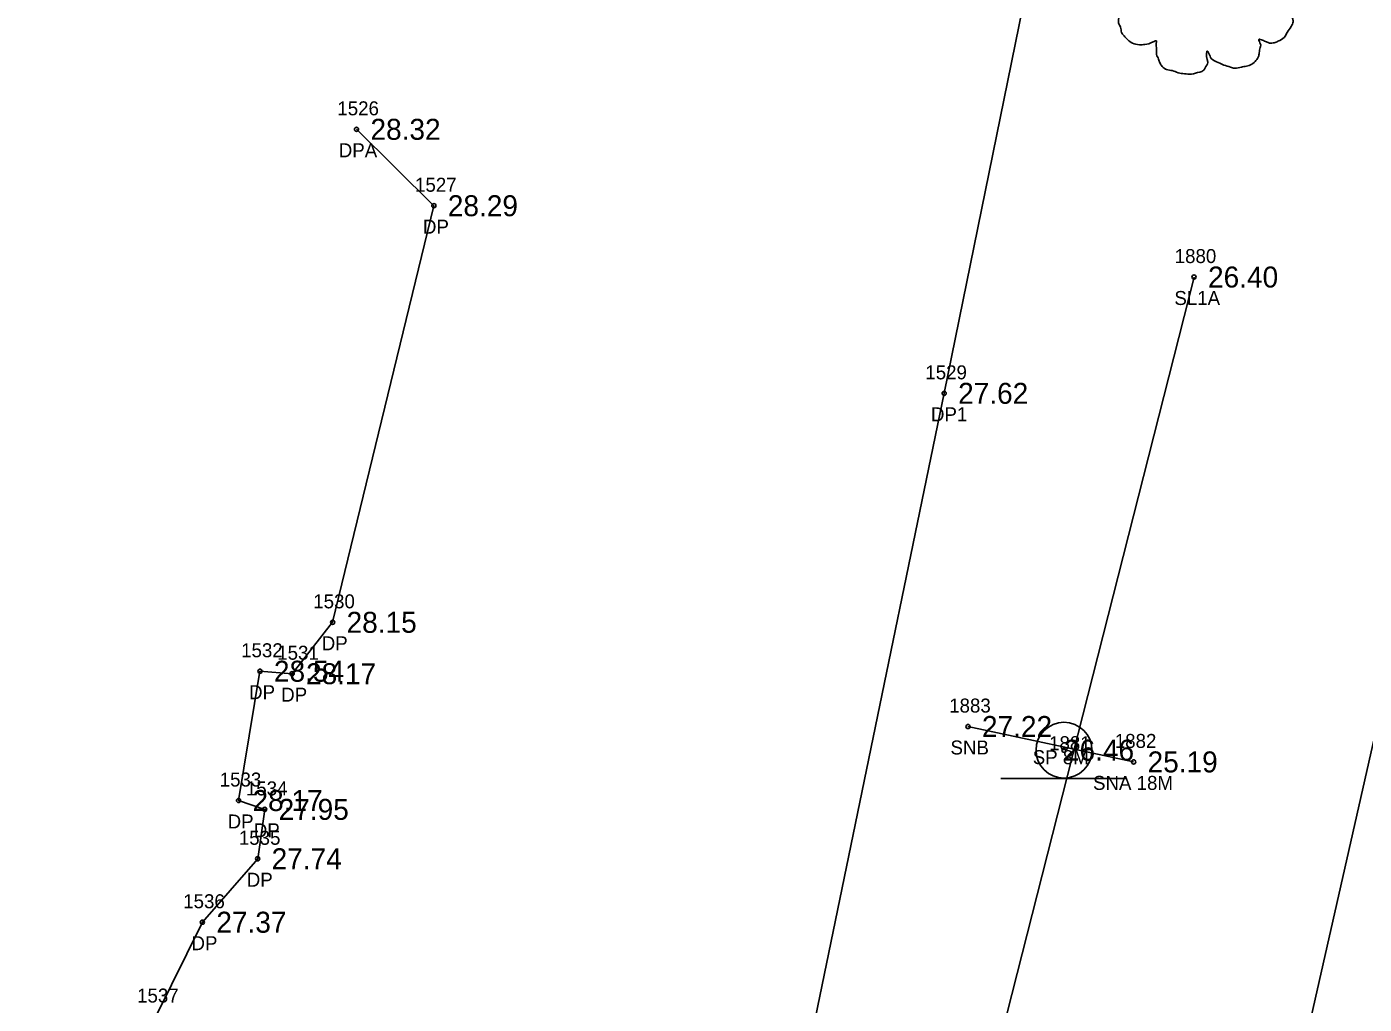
# Model space of a CAD drawing. Extents: x 2654414 to 2656963, y 761776 to 764965.
# Drawn here: x 2655478.7 to 2655574.4, y 762657.4 to 762727.3 of the extents above; entities that cross this region are included whole.
import ezdxf

# ---------------------------------------------------------------- set-up
doc = ezdxf.new("R2010")
doc.units = 0
for name, color, linetype in [('RD_EX_BldgApp', 7, 'Continuous'), ('RD_EX_BldgApp_txCode', 7, 'Continuous'), ('RD_EX_Driveway', 7, 'Continuous'), ('RD_EX_Driveway_txCode', 7, 'Continuous'), ('RD_EX_Road', 7, 'Continuous'), ('RD_EX_TX_BldgApp_ELEV', 7, 'Continuous'), ('RD_EX_TX_Driveway_ELEV', 7, 'Continuous'), ('RD_EX_TX_VEG_ELEV', 7, 'Continuous'), ('RD_EX_VEG', 7, 'Continuous'), ('RD_EX_VEG_txCode', 7, 'Continuous'), ('RD_SMD_Locator', 7, 'Continuous')]:
    doc.layers.add(name, color=color, linetype=linetype)

msp = doc.modelspace()

# ---------------------------------------------------------------- linework, layer by layer
at = {"layer": 'RD_EX_BldgApp'}
for p, q in [((2655557.902, 762674.701), (2655546.048, 762677.232)), ((2655548.4, 762673.514), (2655557.4, 762673.514))]:
    msp.add_line(p, q, dxfattribs=at)
msp.add_circle((2655552.917, 762675.539), 2, dxfattribs=at)
at = {"layer": 'RD_EX_Driveway'}
for points in [[(2655598.992, 762783.09), (2655591.737, 762789.455), (2655575.978, 762787.383), (2655565.187, 762780.326), (2655555.27, 762759.9), (2655550.243, 762730.015), (2655544.342, 762701.065), (2655531.318, 762637.943), (2655527.698, 762630.476), (2655527.209, 762614.176), (2655533.681, 762601.366), (2655541.257, 762592.29), (2655549.192, 762591.56), (2655556.356, 762593.843)], [(2655502.283, 762719.95), (2655507.82, 762714.483), (2655500.575, 762684.686), (2655497.674, 762681.01), (2655495.375, 762681.187), (2655493.84, 762671.94), (2655495.714, 762671.306), (2655495.211, 762667.773), (2655491.253, 762663.235), (2655487.927, 762656.49), (2655481.104, 762632.763), (2655485.711, 762616.615), (2655484.296, 762604.909), (2655505.68, 762598.432), (2655526.949, 762586.383), (2655538.158, 762577.446), (2655543.819, 762568.024), (2655548.114, 762557.141)]]:
    msp.add_lwpolyline(points, dxfattribs=at)
at = {"layer": 'RD_EX_Road'}
msp.add_lwpolyline([(2655700.994, 763232.279), (2655693.552, 763198.573), (2655671.649, 763102.037), (2655649.038, 763001.061), (2655627.271, 762906.233), (2655604.996, 762809.365), (2655598.992, 762783.09), (2655583.655, 762714.137), (2655561.97, 762618.323), (2655556.356, 762593.843), (2655548.114, 762557.141), (2655540.102, 762522.478), (2655518.03, 762425.04), (2655496.479, 762329.558), (2655475.552, 762236.625), (2655473.199, 762226.142), (2655466.574, 762197.504), (2655460.058, 762168.164), (2655454.261, 762143.776), (2655432.5, 762049.878), (2655410.7, 761955.515), (2655388.166, 761858.426), (2655373.501, 761793.951)], dxfattribs=at)
at = {"layer": 'RD_EX_VEG'}
msp.add_lwpolyline([(2655562.228, 762709.383), (2655542.674, 762632.468), (2655541.868, 762617.651)], dxfattribs=at)
for points in [[(2655562.787, 762738.466), (2655562.487, 762738.491), (2655562.162, 762738.391), (2655561.913, 762738.291), (2655561.688, 762738.216), (2655561.463, 762738.116), (2655561.163, 762737.941), (2655560.938, 762737.741), (2655560.813, 762737.491), (2655560.763, 762737.266), (2655560.713, 762736.992), (2655560.713, 762736.817), (2655560.588, 762736.792), (2655560.438, 762736.817), (2655560.188, 762736.892), (2655559.938, 762736.892), (2655559.688, 762736.892), (2655559.339, 762736.867), (2655558.989, 762736.867), (2655558.714, 762736.817), (2655558.389, 762736.767), (2655558.014, 762736.642), (2655557.664, 762736.517), (2655557.365, 762736.267), (2655557.115, 762735.792), (2655556.99, 762735.442), (2655556.84, 762735.192), (2655556.99, 762734.743), (2655557.165, 762734.393), (2655557.19, 762734.193), (2655557.265, 762733.768), (2655557.365, 762733.543), (2655557.489, 762733.343), (2655557.415, 762733.318), (2655557.04, 762733.268), (2655556.74, 762733.168), (2655556.315, 762732.943), (2655556.09, 762732.718), (2655555.99, 762732.394), (2655555.965, 762732.044), (2655555.865, 762731.844), (2655555.79, 762731.569), (2655555.765, 762731.494), (2655555.715, 762731.169), (2655555.815, 762730.719), (2655555.84, 762730.369), (2655555.965, 762730.145), (2655556.115, 762729.97), (2655556.29, 762729.72), (2655556.69, 762729.495), (2655557.015, 762729.395), (2655557.215, 762729.37), (2655557.04, 762728.87), (2655556.99, 762728.52), (2655556.865, 762728.12), (2655556.865, 762728.046), (2655556.815, 762727.571), (2655556.965, 762727.246), (2655557.04, 762726.871), (2655557.215, 762726.646), (2655557.489, 762726.346), (2655557.814, 762726.121), (2655558.314, 762725.996), (2655558.714, 762726.021), (2655559.289, 762726.196), (2655559.539, 762726.271), (2655559.514, 762726.096), (2655559.539, 762725.721), (2655559.539, 762725.297), (2655559.688, 762724.972), (2655559.788, 762724.697), (2655559.938, 762724.447), (2655560.263, 762724.222), (2655560.663, 762724.147), (2655561.088, 762723.997), (2655561.538, 762723.922), (2655562.037, 762723.897), (2655562.637, 762724.047), (2655562.912, 762724.172), (2655563.012, 762724.347), (2655563.212, 762724.722), (2655563.162, 762724.947), (2655563.187, 762725.547), (2655563.287, 762725.372), (2655563.462, 762725.022), (2655563.962, 762724.722), (2655564.361, 762724.547), (2655564.836, 762724.397), (2655565.136, 762724.322), (2655565.611, 762724.397), (2655565.986, 762724.472), (2655566.361, 762724.597), (2655566.66, 762724.872), (2655566.835, 762725.147), (2655566.885, 762725.422), (2655566.96, 762725.796), (2655567.01, 762725.971)], [(2655567.01, 762725.971), (2655566.935, 762726.146), (2655566.885, 762726.396), (2655566.96, 762726.371), (2655567.135, 762726.321), (2655567.41, 762726.196), (2655567.635, 762726.121), (2655567.96, 762726.146), (2655568.235, 762726.246), (2655568.685, 762726.521), (2655568.959, 762726.996), (2655569.234, 762727.396), (2655569.309, 762727.721), (2655569.259, 762727.946), (2655569.234, 762728.445), (2655569.034, 762728.695), (2655568.984, 762728.82), (2655568.884, 762729.22), (2655568.959, 762729.27), (2655569.234, 762729.32), (2655569.609, 762729.445), (2655569.884, 762729.57), (2655570.109, 762729.745), (2655570.184, 762729.97), (2655570.159, 762730.369), (2655570.209, 762730.769), (2655570.134, 762730.919), (2655570.034, 762731.069), (2655569.959, 762731.269), (2655569.809, 762731.419), (2655569.709, 762731.569), (2655569.609, 762731.669), (2655569.484, 762731.819), (2655569.309, 762731.944), (2655569.159, 762731.994), (2655569.109, 762732.144), (2655569.259, 762732.344), (2655569.309, 762732.444), (2655569.334, 762732.668), (2655569.559, 762733.018), (2655569.609, 762733.418), (2655569.559, 762733.843), (2655569.509, 762734.118), (2655569.359, 762734.393), (2655569.159, 762734.643), (2655569.034, 762734.818), (2655568.859, 762734.942), (2655568.535, 762735.067), (2655568.285, 762735.117), (2655567.935, 762735.117), (2655567.735, 762735.167), (2655567.76, 762735.217), (2655567.76, 762735.367), (2655567.76, 762735.642), (2655567.685, 762736.092), (2655567.535, 762736.592), (2655567.535, 762736.617), (2655567.435, 762736.867), (2655567.21, 762737.067), (2655567.035, 762737.166), (2655566.835, 762737.291), (2655566.585, 762737.316), (2655566.286, 762737.316), (2655566.011, 762737.266), (2655565.811, 762737.166), (2655565.636, 762737.042), (2655565.561, 762737.191), (2655565.461, 762737.491), (2655565.411, 762737.641), (2655565.261, 762737.816), (2655565.036, 762738.016), (2655564.586, 762738.141), (2655563.962, 762738.066), (2655563.662, 762737.866), (2655563.512, 762737.691), (2655563.462, 762737.816), (2655563.262, 762738.016), (2655563.162, 762738.191), (2655562.987, 762738.316), (2655562.837, 762738.416), (2655562.737, 762738.466)]]:
    msp.add_spline(points, degree=3, dxfattribs=at)
at = {"layer": 'RD_SMD_Locator'}
for centre in [(2655502.283, 762719.95), (2655507.82, 762714.483), (2655562.228, 762709.383), (2655544.342, 762701.065), (2655500.575, 762684.686), (2655495.375, 762681.187), (2655497.674, 762681.01), (2655546.048, 762677.232), (2655552.917, 762675.539), (2655557.902, 762674.701), (2655493.84, 762671.94), (2655495.714, 762671.306), (2655495.211, 762667.773), (2655491.253, 762663.235)]:
    msp.add_circle(centre, 0.15, dxfattribs=at)

# ---------------------------------------------------------------- texts
at = {"layer": 'RD_EX_BldgApp_txCode'}
for s, p in [('1883', (2655544.702, 762678.232)), ('SNB', (2655544.796, 762675.232)), ('1881', (2655551.854, 762675.539)), ('1882', (2655556.555, 762675.701)), ('SP 8M', (2655550.681, 762674.539)), ('SNA 18M', (2655554.996, 762672.701))]:
    msp.add_text(s, height=1, dxfattribs=at).set_placement(p)
at = {"layer": 'RD_EX_Driveway_txCode'}
for s, p in [('1526', (2655500.913, 762720.95)), ('DPA', (2655501.015, 762717.95)), ('1527', (2655506.473, 762715.483)), ('DP', (2655507.04, 762712.483)), ('1529', (2655542.995, 762702.065)), ('DP1', (2655543.397, 762699.065)), ('1530', (2655499.189, 762685.686)), ('1532', (2655494.028, 762682.187)), ('1531', (2655496.611, 762682.01)), ('DP', (2655499.795, 762682.686)), ('DP', (2655494.595, 762679.187)), ('DP', (2655496.895, 762679.01)), ('1533', (2655492.494, 762672.94)), ('1534', (2655494.368, 762672.306)), ('DP', (2655493.061, 762669.94)), ('1535', (2655493.864, 762668.773)), ('DP', (2655494.934, 762669.306)), ('DP', (2655494.431, 762665.773)), ('1536', (2655489.882, 762664.235)), ('DP', (2655490.473, 762661.235)), ('1537', (2655486.581, 762657.49))]:
    msp.add_text(s, height=1, dxfattribs=at).set_placement(p)
at = {"layer": 'RD_EX_TX_BldgApp_ELEV'}
for s, p in [('27.22', (2655547.048, 762676.482)), ('26.46', (2655552.917, 762674.789)), ('25.19', (2655558.902, 762673.951))]:
    msp.add_text(s, height=1.5, dxfattribs=at).set_placement(p)
at = {"layer": 'RD_EX_TX_Driveway_ELEV'}
for s, p in [('28.32', (2655503.283, 762719.2)), ('28.29', (2655508.82, 762713.733)), ('27.62', (2655545.342, 762700.315)), ('28.15', (2655501.575, 762683.936)), ('28.54', (2655496.375, 762680.437)), ('28.17', (2655498.674, 762680.26)), ('28.17', (2655494.84, 762671.19)), ('27.95', (2655496.714, 762670.556)), ('27.74', (2655496.211, 762667.023)), ('27.37', (2655492.253, 762662.485))]:
    msp.add_text(s, height=1.5, dxfattribs=at).set_placement(p)
at = {"layer": 'RD_EX_TX_VEG_ELEV'}
msp.add_text('26.40', height=1.5, dxfattribs=at).set_placement((2655563.228, 762708.633))
at = {"layer": 'RD_EX_VEG_txCode'}
for s, p in [('1880', (2655560.842, 762710.383)), ('SL1A', (2655560.818, 762707.383))]:
    msp.add_text(s, height=1, dxfattribs=at).set_placement(p)

doc.saveas('drawing.dxf')
